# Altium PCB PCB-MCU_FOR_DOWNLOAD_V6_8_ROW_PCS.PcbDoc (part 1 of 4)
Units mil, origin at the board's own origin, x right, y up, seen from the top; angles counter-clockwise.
Board outline not stored, 4 copper layers (Top, GND1, GND2, Bottom), stack 35.4 mil thick; 280 components, 38 nets, 1144 pads, 944 vias.
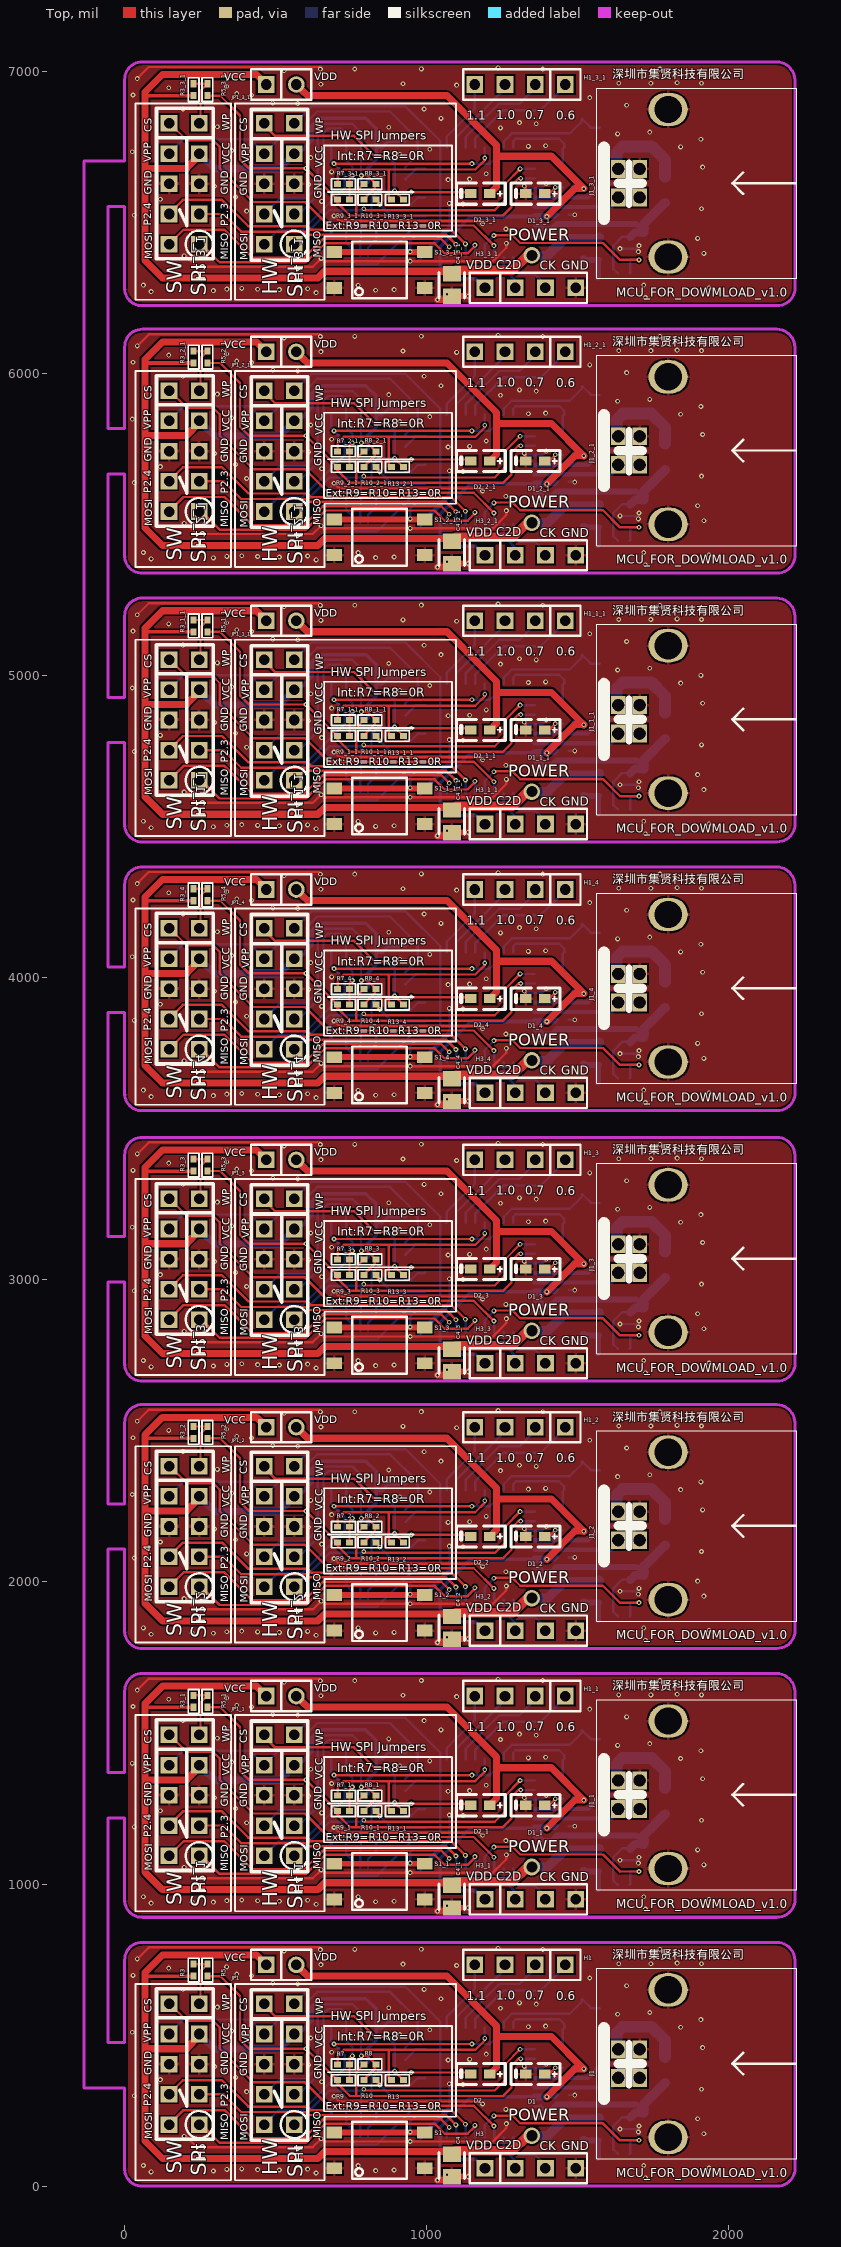
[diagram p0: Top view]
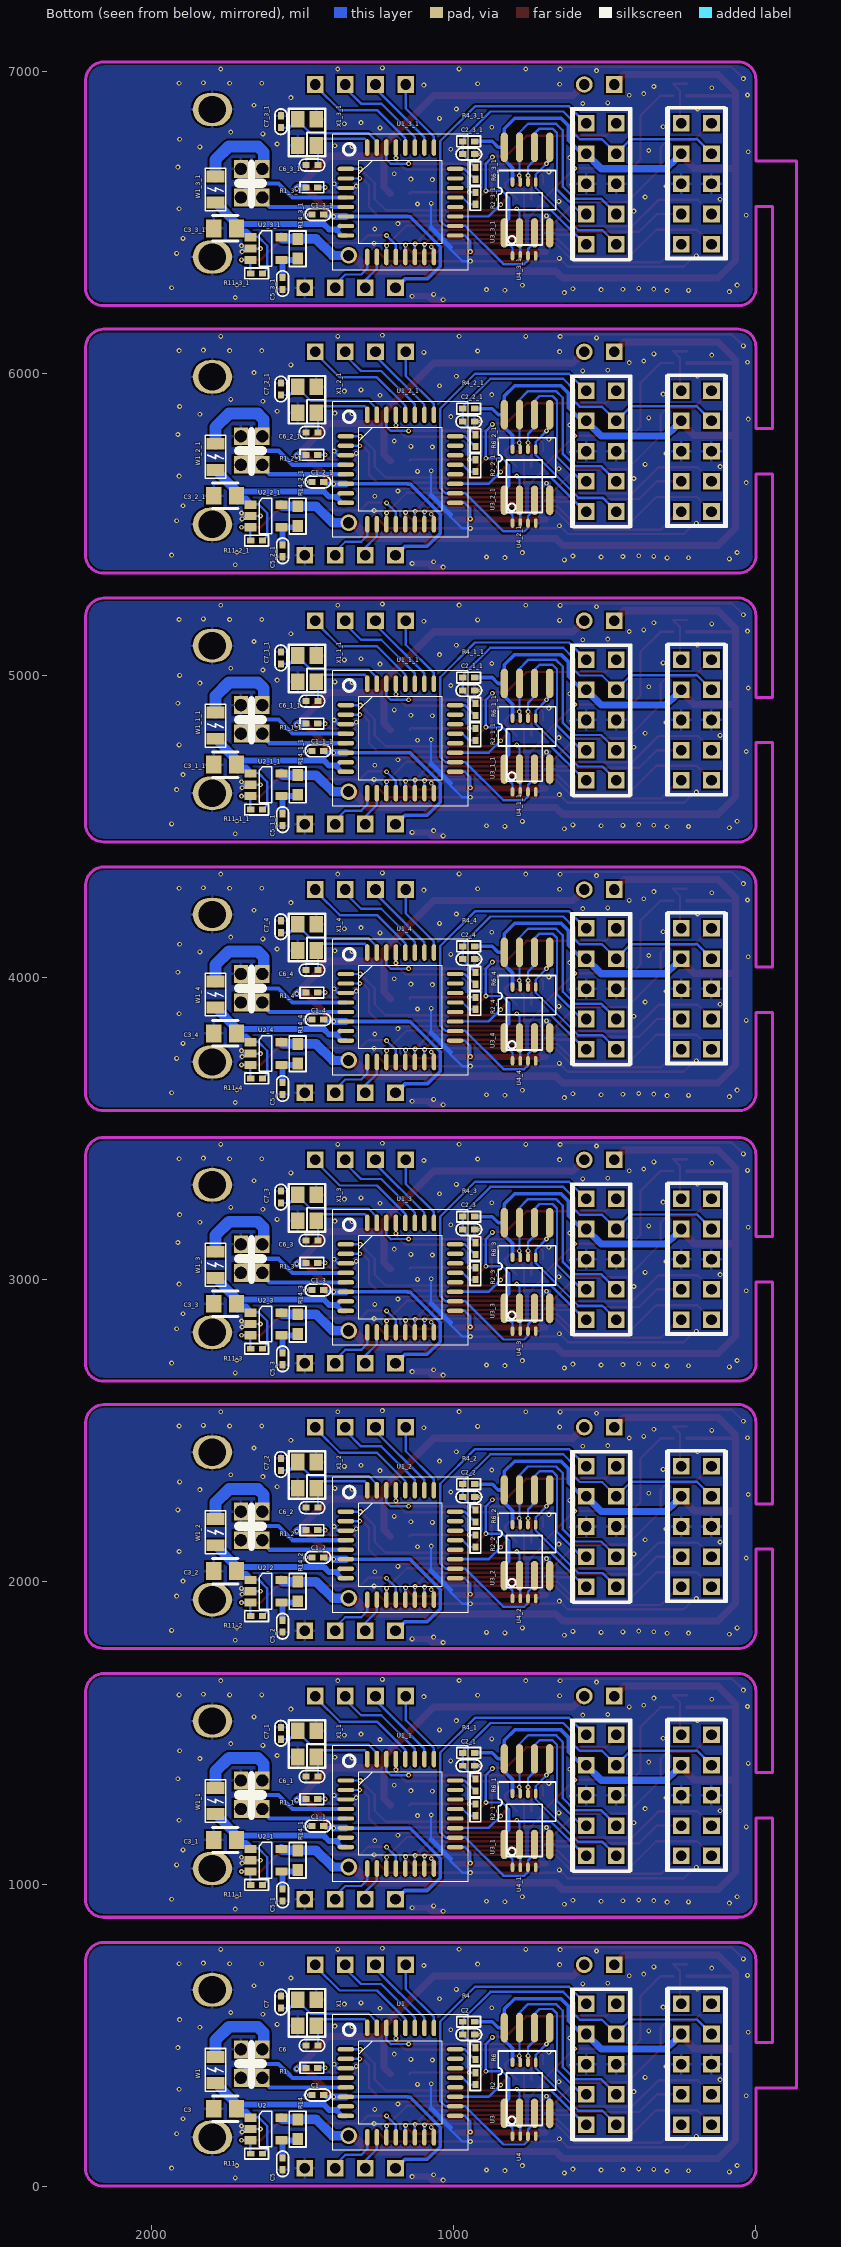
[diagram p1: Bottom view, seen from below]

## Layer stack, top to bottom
Top: signal copper 1.35
Dielectric: dielectric 10, FR-4, Dk 4.3
GND1: signal copper 1.35
Dielectric: dielectric 10, FR-4, Dk 4.3
GND2: signal copper 1.35
Dielectric: dielectric 10, FR-4, Dk 4.3
Bottom: signal copper 1.35

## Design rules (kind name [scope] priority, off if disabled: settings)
Clearance "'Default' PADS rule_18" [All] p1: gap=5.91
Clearance "'Default' PADS rule_15" [IsVia vs IsVia] p2: gap=5.91
ComponentClearance "'Default' PADS rule_12" [All] p1: gap=5.91 collisioncheckmode=3 verticalgap=10 showdistances=FALSE
FlightTimeFalling "'Default' PADS rule_10" [All] p1: maximum=10.00
FlightTimeRising "'Default' PADS rule_9" [All] p1: maximum=10.00
Length "'Default' PADS rule_5" [All] p1: maxlimit=50000 minlimit=0
MatchedLengths "'Default' PADS rule_11" [InNetClass('All Nets')] p1: tolerance=200 checknetsindiffpair=TRUE checkdiffpairvsdiffpair=TRUE checkothers=TRUE
MaxMinImpedance "'Default' PADS rule_8" [All] p1: minimum=50.00 maximum=150.0
ParallelSegment "'Default' PADS rule_7" [All] p1: limit=1000 gap=200
ParallelSegment "'Default' PADS rule_6" [All] p2: limit=1000 gap=200
PlaneClearance "'Default' PADS rule_14" [All] p1: clearance=15
PlaneConnect "Power Plane Connect Style - from global settings" [All] p1: planeconnectstyle=Relief reliefexpansion=20 reliefentries=2 reliefconductorwidth=15 reliefairgap=10
PolygonConnect PolygonConnect_via [IsVia] p1: connectstyle=Direct reliefconductorwidth=10 reliefentries=2 polygonreliefangle="90 Angle"
PolygonConnect PolygonConnect_Pad [All] p2: connectstyle=Relief reliefconductorwidth=10 reliefentries=4 polygonreliefangle="90 Angle"
RoutingLayers "'Default' PADS rule_3" [All] p1: top layer_v5=TRUE mid layer 1_v5=TRUE mid layer 2_v5=TRUE bottom layer_v5=TRUE
RoutingPriority "'Default' PADS rule_2" [All] p1: routingpriority=3
RoutingTopology "'Default' PADS rule" [All] p1: topology=Shortest
RoutingVias "'Default' PADS rule_4" [All] p1: holewidth=37 width=55 viastyle="Through Hole" minholewidth=37 minwidth=55 maxholewidth=37 maxwidth=55
SMDToCorner "'Default' PADS rule_16" [All] p1: distance=59055
SMDToPlane "'Default' PADS rule_17" [All] p1: distance=59055
SilkscreenOverComponentPads [All] p1: minsilkscreentomaskgap=10
SolderMaskExpansion "Solder Mask Expansion from CAM settings" [All] p1: expansion=5
Width "'Default' PADS rule_13" [All] p1: maxlimit=118.11 minlimit=5.91 preferedwidth=7.87
21 further rules are at their usual default settings.

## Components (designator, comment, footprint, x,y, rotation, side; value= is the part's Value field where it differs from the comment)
C1 "C0402" C0402 1450,301.57 r180 bottom
C1_1 "C0402" C0402 1450,1191.57 r180 bottom
C1_1_1 "C0402" C0402 1450,4751.57 r180 bottom
C1_2 "C0402" C0402 1450,2081.57 r180 bottom
C1_2_1 "C0402" C0402 1450,5641.57 r180 bottom
C1_3 "C0402" C0402 1450,2966.57 r180 bottom
C1_3_1 "C0402" C0402 1450,6526.57 r180 bottom
C1_4 "C0402" C0402 1450,3861.57 r180 bottom
C2 "C0402" C0402 950.39,501.57 r0 bottom
C2_1 "C0402" C0402 950.39,1391.57 r0 bottom
C2_1_1 "C0402" C0402 950.39,4951.57 r0 bottom
C2_2 "C0402" C0402 950.39,2281.57 r0 bottom
C2_2_1 "C0402" C0402 950.39,5841.57 r0 bottom
C2_3 "C0402" C0402 950.39,3166.57 r0 bottom
C2_3_1 "C0402" C0402 950.39,6726.57 r0 bottom
C2_4 "C0402" C0402 950.39,4061.57 r0 bottom
C3 "C0805" C0805 1756.69,255.91 r0 bottom
C3_1 "C0805" C0805 1756.69,1145.91 r0 bottom
C3_1_1 "C0805" C0805 1756.69,4705.91 r0 bottom
C3_2 "C0805" C0805 1756.69,2035.91 r0 bottom
C3_2_1 "C0805" C0805 1756.69,5595.91 r0 bottom
C3_3 "C0805" C0805 1756.69,2920.91 r0 bottom
C3_3_1 "C0805" C0805 1756.69,6480.91 r0 bottom
C3_4 "C0805" C0805 1756.69,3815.91 r0 bottom
C4 "C0805" C0805 1083.07,68.11 r270 top
C4_1 "C0805" C0805 1083.07,958.11 r270 top
C4_1_1 "C0805" C0805 1083.07,4518.11 r270 top
C4_2 "C0805" C0805 1083.07,1848.11 r270 top
C4_2_1 "C0805" C0805 1083.07,5408.11 r270 top
C4_3 "C0805" C0805 1083.07,2733.11 r270 top
C4_3_1 "C0805" C0805 1083.07,6293.11 r270 top
C4_4 "C0805" C0805 1083.07,3628.11 r270 top
C5 "C0402" C0402 1566.54,73.62 r90 bottom
C5_1 "C0402" C0402 1566.54,963.62 r90 bottom
C5_1_1 "C0402" C0402 1566.54,4523.62 r90 bottom
C5_2 "C0402" C0402 1566.54,1853.62 r90 bottom
C5_2_1 "C0402" C0402 1566.54,5413.62 r90 bottom
C5_3 "C0402" C0402 1566.54,2738.62 r90 bottom
C5_3_1 "C0402" C0402 1566.54,6298.62 r90 bottom
C5_4 "C0402" C0402 1566.54,3633.62 r90 bottom
C6 "C0402" C0402 1469.29,465.75 r0 bottom
C6_1 "C0402" C0402 1469.29,1355.75 r0 bottom
C6_1_1 "C0402" C0402 1469.29,4915.75 r0 bottom
C6_2 "C0402" C0402 1469.29,2245.75 r0 bottom
C6_2_1 "C0402" C0402 1469.29,5805.75 r0 bottom
C6_3 "C0402" C0402 1469.29,3130.75 r0 bottom
C6_3_1 "C0402" C0402 1469.29,6690.75 r0 bottom
C6_4 "C0402" C0402 1469.29,4025.75 r0 bottom
C7 "C0402" C0402 1572.44,609.06 r90 bottom
C7_1 "C0402" C0402 1572.44,1499.06 r90 bottom
C7_1_1 "C0402" C0402 1572.44,5059.06 r90 bottom
C7_2 "C0402" C0402 1572.44,2389.06 r90 bottom
C7_2_1 "C0402" C0402 1572.44,5949.06 r90 bottom
C7_3 "C0402" C0402 1572.44,3274.06 r90 bottom
C7_3_1 "C0402" C0402 1572.44,6834.06 r90 bottom
C7_4 "C0402" C0402 1572.44,4169.06 r90 bottom
D1 "LED0603" LED0603 1358.27,370.87 r0 top
D1_1 "LED0603" LED0603 1358.27,1260.87 r0 top
D1_1_1 "LED0603" LED0603 1358.27,4820.87 r0 top
D1_2 "LED0603" LED0603 1358.27,2150.87 r0 top
D1_2_1 "LED0603" LED0603 1358.27,5710.87 r0 top
D1_3 "LED0603" LED0603 1358.27,3035.87 r0 top
D1_3_1 "LED0603" LED0603 1358.27,6595.87 r0 top
D1_4 "LED0603" LED0603 1358.27,3930.87 r0 top
D2 "LED0603" LED0603 1177.17,370.87 r0 top
D2_1 "LED0603" LED0603 1177.17,1260.87 r0 top
D2_1_1 "LED0603" LED0603 1177.17,4820.87 r0 top
D2_2 "LED0603" LED0603 1177.17,2150.87 r0 top
D2_2_1 "LED0603" LED0603 1177.17,5710.87 r0 top
D2_3 "LED0603" LED0603 1177.17,3035.87 r0 top
D2_3_1 "LED0603" LED0603 1177.17,6595.87 r0 top
D2_4 "LED0603" LED0603 1177.17,3930.87 r0 top
H1 "H04X1_SQUARE" H04X1_SQUARE 1459.06,732.28 r180 top
H1_1 "H04X1_SQUARE" H04X1_SQUARE 1459.06,1622.28 r180 top
H1_1_1 "H04X1_SQUARE" H04X1_SQUARE 1459.06,5182.28 r180 top
H1_2 "H04X1_SQUARE" H04X1_SQUARE 1459.06,2512.28 r180 top
H1_2_1 "H04X1_SQUARE" H04X1_SQUARE 1459.06,6072.28 r180 top
H1_3 "H04X1_SQUARE" H04X1_SQUARE 1459.06,3397.28 r180 top
H1_3_1 "H04X1_SQUARE" H04X1_SQUARE 1459.06,6957.28 r180 top
H1_4 "H04X1_SQUARE" H04X1_SQUARE 1459.06,4292.28 r180 top
H2 "JH2X5" JH2X5 196.85,403.54 r90 top
H2_1 "JH2X5" JH2X5 196.85,1293.54 r90 top
H2_1_1 "JH2X5" JH2X5 196.85,4853.54 r90 top
H2_2 "JH2X5" JH2X5 196.85,2183.54 r90 top
H2_2_1 "JH2X5" JH2X5 196.85,5743.54 r90 top
H2_3 "JH2X5" JH2X5 196.85,3068.54 r90 top
H2_3_1 "JH2X5" JH2X5 196.85,6628.54 r90 top
H2_4 "JH2X5" JH2X5 196.85,3963.54 r90 top
H3 "H04X1_SQUARE" H04X1_SQUARE 1192.91,59.06 r0 top
H3_1 "H04X1_SQUARE" H04X1_SQUARE 1192.91,949.06 r0 top
H3_1_1 "H04X1_SQUARE" H04X1_SQUARE 1192.91,4509.06 r0 top
H3_2 "H04X1_SQUARE" H04X1_SQUARE 1192.91,1839.06 r0 top
H3_2_1 "H04X1_SQUARE" H04X1_SQUARE 1192.91,5399.06 r0 top
H3_3 "H04X1_SQUARE" H04X1_SQUARE 1192.91,2724.06 r0 top
H3_3_1 "H04X1_SQUARE" H04X1_SQUARE 1192.91,6284.06 r0 top
H3_4 "H04X1_SQUARE" H04X1_SQUARE 1192.91,3619.06 r0 top
H4 "JH2X5" JH2X5 511.81,403.54 r90 top
H4_1 "JH2X5" JH2X5 511.81,1293.54 r90 top
H4_1_1 "JH2X5" JH2X5 511.81,4853.54 r90 top
H4_2 "JH2X5" JH2X5 511.81,2183.54 r90 top
H4_2_1 "JH2X5" JH2X5 511.81,5743.54 r90 top
H4_3 "JH2X5" JH2X5 511.81,3068.54 r90 top
H4_3_1 "JH2X5" JH2X5 511.81,6628.54 r90 top
H4_4 "JH2X5" JH2X5 511.81,3963.54 r90 top
J1 "USB-6" USB-6 1633.86,405.51 r90 top
J1_1 "USB-6" USB-6 1633.86,1295.51 r90 top
J1_1_1 "USB-6" USB-6 1633.86,4855.51 r90 top
J1_2 "USB-6" USB-6 1633.86,2185.51 r90 top
J1_2_1 "USB-6" USB-6 1633.86,5745.51 r90 top
J1_3 "USB-6" USB-6 1633.86,3070.51 r90 top
J1_3_1 "USB-6" USB-6 1633.86,6630.51 r90 top
J1_4 "USB-6" USB-6 1633.86,3965.51 r90 top
JP1 "H02X1" H02X1 468.11,732.28 r0 top
JP1_1 "H02X1" H02X1 468.11,1622.28 r0 top
JP1_1_1 "H02X1" H02X1 468.11,5182.28 r0 top
JP1_2 "H02X1" H02X1 468.11,2512.28 r0 top
JP1_2_1 "H02X1" H02X1 468.11,6072.28 r0 top
JP1_3 "H02X1" H02X1 468.11,3397.28 r0 top
JP1_3_1 "H02X1" H02X1 468.11,6957.28 r0 top
JP1_4 "H02X1" H02X1 468.11,4292.28 r0 top
R1 "R0402" R0402 1470.08,391.34 r0 bottom
R1_1 "R0402" R0402 1470.08,1281.34 r0 bottom
R1_1_1 "R0402" R0402 1470.08,4841.34 r0 bottom
R1_2 "R0402" R0402 1470.08,2171.34 r0 bottom
R1_2_1 "R0402" R0402 1470.08,5731.34 r0 bottom
R1_3 "R0402" R0402 1470.08,3056.34 r0 bottom
R1_3_1 "R0402" R0402 1470.08,6616.34 r0 bottom
R1_4 "R0402" R0402 1470.08,3951.34 r0 bottom
R2 "R0402" R0402 928.35,355.51 r270 bottom
R2_1 "R0402" R0402 928.35,1245.51 r270 bottom
R2_1_1 "R0402" R0402 928.35,4805.51 r270 bottom
R2_2 "R0402" R0402 928.35,2135.51 r270 bottom
R2_2_1 "R0402" R0402 928.35,5695.51 r270 bottom
R2_3 "R0402" R0402 928.35,3020.51 r270 bottom
R2_3_1 "R0402" R0402 928.35,6580.51 r270 bottom
R2_4 "R0402" R0402 928.35,3915.51 r270 bottom
R3 "R0402" R0402 227.95,714.96 r270 top
R3_1 "R0402" R0402 227.95,1604.96 r270 top
R3_1_1 "R0402" R0402 227.95,5164.96 r270 top
R3_2 "R0402" R0402 227.95,2494.96 r270 top
R3_2_1 "R0402" R0402 227.95,6054.96 r270 top
R3_3 "R0402" R0402 227.95,3379.96 r270 top
R3_3_1 "R0402" R0402 227.95,6939.96 r270 top
R3_4 "R0402" R0402 227.95,4274.96 r270 top
R4 "R0402" R0402 950.39,544.09 r180 bottom
R4_1 "R0402" R0402 950.39,1434.09 r180 bottom
R4_1_1 "R0402" R0402 950.39,4994.09 r180 bottom
R4_2 "R0402" R0402 950.39,2324.09 r180 bottom
R4_2_1 "R0402" R0402 950.39,5884.09 r180 bottom
R4_3 "R0402" R0402 950.39,3209.09 r180 bottom
R4_3_1 "R0402" R0402 950.39,6769.09 r180 bottom
R4_4 "R0402" R0402 950.39,4104.09 r180 bottom
R5 "R0402" R0402 274.02,714.96 r270 top
R5_1 "R0402" R0402 274.02,1604.96 r270 top
R5_1_1 "R0402" R0402 274.02,5164.96 r270 top
R5_2 "R0402" R0402 274.02,2494.96 r270 top
R5_2_1 "R0402" R0402 274.02,6054.96 r270 top
R5_3 "R0402" R0402 274.02,3379.96 r270 top
R5_3_1 "R0402" R0402 274.02,6939.96 r270 top
R5_4 "R0402" R0402 274.02,4274.96 r270 top
R6 "R0402" R0402 928.35,438.19 r90 bottom
R6_1 "R0402" R0402 928.35,1328.19 r90 bottom
R6_1_1 "R0402" R0402 928.35,4888.19 r90 bottom
R6_2 "R0402" R0402 928.35,2218.19 r90 bottom
R6_2_1 "R0402" R0402 928.35,5778.19 r90 bottom
R6_3 "R0402" R0402 928.35,3103.19 r90 bottom
R6_3_1 "R0402" R0402 928.35,6663.19 r90 bottom
R6_4 "R0402" R0402 928.35,3998.19 r90 bottom
R7 "R0402" R0402 724.41,402.76 r180 top
R7_1 "R0402" R0402 724.41,1292.76 r180 top
R7_1_1 "R0402" R0402 724.41,4852.76 r180 top
R7_2 "R0402" R0402 724.41,2182.76 r180 top
R7_2_1 "R0402" R0402 724.41,5742.76 r180 top
R7_3 "R0402" R0402 724.41,3067.76 r180 top
R7_3_1 "R0402" R0402 724.41,6627.76 r180 top
R7_4 "R0402" R0402 724.41,3962.76 r180 top
R8 "R0402" R0402 811.81,402.76 r0 top
R8_1 "R0402" R0402 811.81,1292.76 r0 top
R8_1_1 "R0402" R0402 811.81,4852.76 r0 top
R8_2 "R0402" R0402 811.81,2182.76 r0 top
R8_2_1 "R0402" R0402 811.81,5742.76 r0 top
R8_3 "R0402" R0402 811.81,3067.76 r0 top
R8_3_1 "R0402" R0402 811.81,6627.76 r0 top
R8_4 "R0402" R0402 811.81,3962.76 r0 top
R9 "R0402" R0402 724.41,351.18 r180 top
R9_1 "R0402" R0402 724.41,1241.18 r180 top
R9_1_1 "R0402" R0402 724.41,4801.18 r180 top
R9_2 "R0402" R0402 724.41,2131.18 r180 top
R9_2_1 "R0402" R0402 724.41,5691.18 r180 top
R9_3 "R0402" R0402 724.41,3016.18 r180 top
R9_3_1 "R0402" R0402 724.41,6576.18 r180 top
R9_4 "R0402" R0402 724.41,3911.18 r180 top
R10 "R0402" R0402 811.81,351.18 r180 top
R10_1 "R0402" R0402 811.81,1241.18 r180 top
R10_1_1 "R0402" R0402 811.81,4801.18 r180 top
R10_2 "R0402" R0402 811.81,2131.18 r180 top
R10_2_1 "R0402" R0402 811.81,5691.18 r180 top
R10_3 "R0402" R0402 811.81,3016.18 r180 top
R10_3_1 "R0402" R0402 811.81,6576.18 r180 top
R10_4 "R0402" R0402 811.81,3911.18 r180 top
R11 "R0402" R0402 1652.36,107.09 r0 bottom
R11_1 "R0402" R0402 1652.36,997.09 r0 bottom
R11_1_1 "R0402" R0402 1652.36,4557.09 r0 bottom
R11_2 "R0402" R0402 1652.36,1887.09 r0 bottom
R11_2_1 "R0402" R0402 1652.36,5447.09 r0 bottom
R11_3 "R0402" R0402 1652.36,2772.09 r0 bottom
R11_3_1 "R0402" R0402 1652.36,6332.09 r0 bottom
R11_4 "R0402" R0402 1652.36,3667.09 r0 bottom
R13 "R0402" R0402 902.76,351.18 r0 top
R13_1 "R0402" R0402 902.76,1241.18 r0 top
R13_1_1 "R0402" R0402 902.76,4801.18 r0 top
R13_2 "R0402" R0402 902.76,2131.18 r0 top
R13_2_1 "R0402" R0402 902.76,5691.18 r0 top
R13_3 "R0402" R0402 902.76,3016.18 r0 top
R13_3_1 "R0402" R0402 902.76,6576.18 r0 top
R13_4 "R0402" R0402 902.76,3911.18 r0 top
R14 "R0603" R0603 1516.93,188.58 r270 bottom
R14_1 "R0603" R0603 1516.93,1078.58 r270 bottom
R14_1_1 "R0603" R0603 1516.93,4638.58 r270 bottom
R14_2 "R0603" R0603 1516.93,1968.58 r270 bottom
R14_2_1 "R0603" R0603 1516.93,5528.58 r270 bottom
R14_3 "R0603" R0603 1516.93,2853.58 r270 bottom
R14_3_1 "R0603" R0603 1516.93,6413.58 r270 bottom
R14_4 "R0603" R0603 1516.93,3748.58 r270 bottom
S1 "4PIN_SWITCH_SMD_4.5MM" 4PIN_SWITCH_SMD_4.5MM 843.7,118.11 r90 top
S1_1 "4PIN_SWITCH_SMD_4.5MM" 4PIN_SWITCH_SMD_4.5MM 843.7,1008.11 r90 top
S1_1_1 "4PIN_SWITCH_SMD_4.5MM" 4PIN_SWITCH_SMD_4.5MM 843.7,4568.11 r90 top
S1_2 "4PIN_SWITCH_SMD_4.5MM" 4PIN_SWITCH_SMD_4.5MM 843.7,1898.11 r90 top
S1_2_1 "4PIN_SWITCH_SMD_4.5MM" 4PIN_SWITCH_SMD_4.5MM 843.7,5458.11 r90 top
S1_3 "4PIN_SWITCH_SMD_4.5MM" 4PIN_SWITCH_SMD_4.5MM 843.7,2783.11 r90 top
S1_3_1 "4PIN_SWITCH_SMD_4.5MM" 4PIN_SWITCH_SMD_4.5MM 843.7,6343.11 r90 top
S1_4 "4PIN_SWITCH_SMD_4.5MM" 4PIN_SWITCH_SMD_4.5MM 843.7,3678.11 r90 top
U1 "LQFP-32" LQFP-32 1357.09,452.76 r180 bottom
U1_1 "LQFP-32" LQFP-32 1357.09,1342.76 r180 bottom
U1_1_1 "LQFP-32" LQFP-32 1357.09,4902.76 r180 bottom
U1_2 "LQFP-32" LQFP-32 1357.09,2232.76 r180 bottom
U1_2_1 "LQFP-32" LQFP-32 1357.09,5792.76 r180 bottom
U1_3 "LQFP-32" LQFP-32 1357.09,3117.76 r180 bottom
U1_3_1 "LQFP-32" LQFP-32 1357.09,6677.76 r180 bottom
U1_4 "LQFP-32" LQFP-32 1357.09,4012.76 r180 bottom
U2 "SOT23-5_SGM2019" SOT23-5_SGM2019 1673.23,188.98 r180 bottom
U2_1 "SOT23-5_SGM2019" SOT23-5_SGM2019 1673.23,1078.98 r180 bottom
U2_1_1 "SOT23-5_SGM2019" SOT23-5_SGM2019 1673.23,4638.98 r180 bottom
U2_2 "SOT23-5_SGM2019" SOT23-5_SGM2019 1673.23,1968.98 r180 bottom
U2_2_1 "SOT23-5_SGM2019" SOT23-5_SGM2019 1673.23,5528.98 r180 bottom
U2_3 "SOT23-5_SGM2019" SOT23-5_SGM2019 1673.23,2853.98 r180 bottom
U2_3_1 "SOT23-5_SGM2019" SOT23-5_SGM2019 1673.23,6413.98 r180 bottom
U2_4 "SOT23-5_SGM2019" SOT23-5_SGM2019 1673.23,3748.98 r180 bottom
U3 "SO8W" SO8W 757.48,382.68 r180 bottom
U3_1 "SO8W" SO8W 757.48,1272.68 r180 bottom
U3_1_1 "SO8W" SO8W 757.48,4832.68 r180 bottom
U3_2 "SO8W" SO8W 757.48,2162.68 r180 bottom
U3_2_1 "SO8W" SO8W 757.48,5722.68 r180 bottom
U3_3 "SO8W" SO8W 757.48,3047.68 r180 bottom
U3_3_1 "SO8W" SO8W 757.48,6607.68 r180 bottom
U3_4 "SO8W" SO8W 757.48,3942.68 r180 bottom
U4 "SO8-TSS" SO8-TSS 805.51,165.35 r90 bottom
U4_1 "SO8-TSS" SO8-TSS 805.51,1055.35 r90 bottom
U4_1_1 "SO8-TSS" SO8-TSS 805.51,4615.35 r90 bottom
U4_2 "SO8-TSS" SO8-TSS 805.51,1945.35 r90 bottom
U4_2_1 "SO8-TSS" SO8-TSS 805.51,5505.35 r90 bottom
U4_3 "SO8-TSS" SO8-TSS 805.51,2830.35 r90 bottom
U4_3_1 "SO8-TSS" SO8-TSS 805.51,6390.35 r90 bottom
U4_4 "SO8-TSS" SO8-TSS 805.51,3725.35 r90 bottom
W1 "SMD0805" SMD0805 1788.98,384.65 r90 bottom
W1_1 "SMD0805" SMD0805 1788.98,1274.65 r90 bottom
W1_1_1 "SMD0805" SMD0805 1788.98,4834.65 r90 bottom
W1_2 "SMD0805" SMD0805 1788.98,2164.65 r90 bottom
W1_2_1 "SMD0805" SMD0805 1788.98,5724.65 r90 bottom
W1_3 "SMD0805" SMD0805 1788.98,3049.65 r90 bottom
W1_3_1 "SMD0805" SMD0805 1788.98,6609.65 r90 bottom
W1_4 "SMD0805" SMD0805 1788.98,3944.65 r90 bottom
X1 "3225_4" 3225_4 1485.83,573.62 r90 bottom
X1_1 "3225_4" 3225_4 1485.83,1463.62 r90 bottom
X1_1_1 "3225_4" 3225_4 1485.83,5023.62 r90 bottom
X1_2 "3225_4" 3225_4 1485.83,2353.62 r90 bottom
X1_2_1 "3225_4" 3225_4 1485.83,5913.62 r90 bottom
X1_3 "3225_4" 3225_4 1485.83,3238.62 r90 bottom
X1_3_1 "3225_4" 3225_4 1485.83,6798.62 r90 bottom
X1_4 "3225_4" 3225_4 1485.83,4133.62 r90 bottom

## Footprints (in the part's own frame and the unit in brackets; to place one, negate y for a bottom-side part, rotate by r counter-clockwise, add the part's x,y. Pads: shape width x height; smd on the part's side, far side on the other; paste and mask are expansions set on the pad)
4PIN_SWITCH_SMD_4.5MM [mm]
  rect 1x1.3 smd: 1(-1.5,3.8) 2(1.5,3.8) 3(-1.5,-3.8) 4(1.5,-3.8)
  silkscreen extent -2.37,-2.3 2.4,2.3
3225_4 [mm]
  rect 1.4x1.15 smd: 1(-1.1,-0.782) 2(1.1,-0.782) 3(1.1,0.782) 4(-1.1,0.782)
  silkscreen extent -2,-1.52 2,1.52
C0402 [mm]
  rect 0.6x0.5 smd: 1(-0.5,0) 2(0.5,0)
  silkscreen extent -1.07,-0.5 1.07,0.5
C0805 [mil]
  rect 50.98x59.02 smd: 1(-37.48,0) 2(37.48,0)
  silkscreen extent -43,-42 43,42
H02X1 [mil]
  rect 55x55 / inner round 55 / far side rect 55x55 hole 35: 1(0,0)
  round 55 hole 35: 2(100,0)
  silkscreen extent -50,-50 150,50
H04X1_SQUARE [mil]
  rect 55x55 hole 35: 1(0,0) 2(100,0) 3(200,0) 4(300,0)
  silkscreen extent -50,-50 338,50
JH2X5 [mil]
  rect 55x55 hole 35: 1(-200,-50) 2(-200,50) 3(-100,-50) 4(-100,50) 5(0,-50) 6(0,50) 7(100,-50) 8(100,50) 9(200,-50) 10(200,50)
  silkscreen extent -245,-95 -155,-5
LED0603 [mil]
  rect 38x30 smd paste+1.18 mask+1.18: 1(-31,0) 2(31.99,0)
  silkscreen extent -79,-35 83,35
LQFP-32 [mm]
  oval 1.4x0.37 smd: 1(0,0) 2(0,-0.8) 3(0,-1.6) 4(0,-2.4) 5(0,-3.2) 6(0,-4) 7(0,-4.8) 8(0,-5.6) 17(9.2,-5.6) 18(9.2,-4.8) 19(9.2,-4) 20(9.2,-3.2) 21(9.2,-2.4) 22(9.2,-1.6) 23(9.2,-0.8) 24(9.2,0)
  oval 0.37x1.4 smd: 9(1.8,-7.4) 10(2.6,-7.4) 11(3.4,-7.4) 12(4.2,-7.4) 13(5,-7.4) 14(5.8,-7.4) 15(6.6,-7.4) 16(7.4,-7.4) 25(7.4,1.8) 26(6.6,1.8) 27(5.8,1.8) 28(5,1.8) 29(4.2,1.8) 30(3.4,1.8) 31(2.6,1.8) 32(1.8,1.8)
  silkscreen extent -1.1,-8.5 10.3,2.9
R0402 [mm]
  rect 0.6x0.5 smd: 1(-0.5,0) 2(0.5,0)
  silkscreen extent -1,-0.45 1,0.45
R0603 [mm]
  rect 1x0.9 smd: 1(-0.826,0) 2(0.826,0)
  silkscreen extent -1.5,-0.7 1.5,0.7
SMD0805 [mm]
  rect 1x1.5 smd paste-0.1 mask-0.1: 1(-1.1,0) 2(1.1,0)
  silkscreen extent -1.8,-0.85 1.8,0.85
SO8-TSS [mm]
  oval 0.8x0.3 smd: 1(0,0) 2(0,-0.65) 3(0,-1.3) 4(0,-1.95) 5(6.2,-1.95) 6(6.2,-1.3) 7(6.2,-0.65) 8(6.2,0)
  silkscreen extent 0.9,-2.5 5.3,0.5
SO8W [mil]
  oval 24x97.62 smd paste-11.81 mask-11.81: 1(-75,-141.73) 2(-25,-141.73) 3(25,-141.73) 4(75,-141.73) 5(75,141.73) 6(25,141.73) 7(-25,141.73) 8(-75,141.73)
  silkscreen extent -95,-65 95,65
SOT23-5_SGM2019 [mm]
  rect 1x0.69 smd: 1(0,0.95) 2(0,0) 3(0,-0.95) 4(2.6,-0.95) 5(2.6,0.95)
  silkscreen extent 0.76,-1.5 1.8,1.5
USB-6 [mm]
  rect 1.5x1.2 / inner rect 0x0 / far side rect 1.5x1.2 hole 1: 1(1.2,0) 2(-1.2,0) 3(-1.2,-1.8) 4(1.2,-1.8)
  oval 2.8x3.3 / inner round 0 / far side oval 2.8x3.3 hole 2.3: 5(6.2,-4.2) 6(-6.2,-4.2)
  silkscreen extent -8,-15 8,1.8

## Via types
v1: diameter 16/16/16/16 (per signal layer), hole 8, Top to Bottom, 936 vias
v2: diameter 55/55/55/55 (per signal layer), hole 37, Top to Bottom, 8 vias

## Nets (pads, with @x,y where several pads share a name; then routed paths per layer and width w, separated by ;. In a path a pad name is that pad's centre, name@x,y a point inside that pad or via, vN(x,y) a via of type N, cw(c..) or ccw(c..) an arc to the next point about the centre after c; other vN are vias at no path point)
+5V: C3.1 R11.1 U1.7 U1.8 U2.1 W1.1 | length 791.9
  Bottom w7.87: R11.1@1632.68,107.09 1619.29,120.47 1617.72,120.47 1617.72,198.57 1646.88,227.73 1647.02,227.73 1647.24,227.95 1673.23,227.95 1674.02,227.18 U2.1@1673.23,226.38
  Bottom w9.84: U1.7@1357.09,263.78 U1.7@1376.38,263.78
  Bottom w15.75: U1.8@1357.09,232.28 1370.87,232.28 1389.37,250.79 U1.7@1376.38,263.78
  Bottom w19.68: 1389.37,250.79 1391.14,252.56 1412.8,252.56 1430.31,270.08 1692.05,270.08 1718.9,256.07 C3.1@1719.21,255.91
  Bottom w27.56: U2.1@1674.02,227.18 1688.98,242.52 C3.1@1712.99,242.52
  Bottom w31.5: C3.1@1712.99,242.52 1718.82,242.52 C3.1@1718.9,245.19 ; W1.1@1788.98,341.34 1718.9,271.26 1718.9,256.07 1718.9,255.91 C3.1@1718.9,245.19 ; C3.1@1718.9,245.19 1718.9,243.23 C3.1@1719.21,255.91 C3.1@1718.9,245.19
C2CK: H3.3 U1.9 | length 186.3
  Bottom w7.87: U1.9@1286.22,161.42 1286.22,123.62 1306.5,103.35 1359.06,103.35 1398.13,64.27 1400.79,61.61 H3.3@1392.91,59.06
C2D: H3.2 U1.10 | length 130.9
  Bottom w7.87: U1.10@1254.72,161.42 1254.72,122.05 1297.01,79.76 1297.01,59.26 1300.59,59.26 H3.2@1292.91,59.06
GGND: C1.1 C2.1 C3.2 C4.2 C5.1 C6.2 C7.2 D1.1 H2.5 H2.6 H3.4 H4.5 H4.6 J1.4 J1.5 J1.6 S1.1 S1.3 U1.3 U2.2 U3.4 U4.4 X1.2 X1.4 | length 2977.8
  Top w7.87: v1(41.34,751.97) 79.53,790.16 644.09,790.16 648.03,786.22 v1(648.03,783.07) ; v1(196.85,164.96) 202.76,164.96 238.58,129.13 622.83,129.13 v1@648.83,155.13 ; v1(692.91,297.24) 693.31,297.24 710.63,279.92 1176.77,279.92 v1(1185.04,271.65) ; v1(1263.78,206.69) 1263.39,192.13 1218.9,147.64 v1(944.88,147.64) 660.24,147.64 649.21,154.89 v1@648.83,155.13 ; v1(1322.83,396.06) 1327.27,391.63 D1.1@1327.27,370.87 ; v1@648.83,155.13 646.46,156.69 v1(650.39,156.69) v1@648.83,155.13
  Top w19.68: C4.2@1083.07,30.63 1083.94,31.5 v1(1137.8,31.5)
  Top w22.05: v1(1035.43,19.69) 1072.13,19.69 1078.39,25.95 C4.2@1083.07,30.63
  Bottom w7.87: v1(692.91,297.24) 692.91,296.65 U3.4@682.48,286.22 ; v1(910.63,501.57) 911.02,501.57 C2.1@930.71,501.57 ; v1(944.88,147.64) 972.05,147.64 1011.02,186.61 1011.02,193.7 ; v1(1074.8,338.58) 1075.2,338.19 1075.2,257.87 ; v1(1322.83,396.06) 1328.6,390.3 1328.6,390.01 1328.85,389.76 U1.3@1357.09,389.76 1381.89,389.76 v1(1395.67,403.54) ; C1.1@1469.68,301.58 1489.76,301.58 v1(1490.16,301.18) ; v1(1639.76,188.98) U2.2@1673.23,188.98 1690.94,188.98 U2.2@1691.73,188.19 ; v1(1700.79,179.13) U2.2@1691.73,188.19 ; v1(1702.76,198.82) 1692.13,188.19 U2.2@1691.73,188.19 ; U3.4@682.48,286.22 U3.4@682.48,240.94 682.48,238 686.32,241.84 U3.4@682.48,286.22
  Bottom w15.75: 1011.02,193.7 1075.2,257.87
  other v1: 1723.62,27.17 1066.93,37.4 633.86,43.31 87.4,46.85 293.7,50 222.83,50.79 830.71,51.18 512.2,53.15 891.73,53.15 338.19,55.12 440.16,54.72 605.51,56.3 387.8,57.09 1934.25,59.45 61.81,68.11 772.83,67.72 1718.5,68.11 1917.32,173.23 1896.46,222.83 1261.81,253.94 31.5,299.21 403.54,312.99 1909.45,320.87 1120.08,336.61 651.97,345.28 118.11,352.36 366.54,359.84 297.24,395.67 608.27,401.18 1070.87,417.32 1141.73,419.29 1196.85,437.01 685.04,442.91 1913.39,458.66 616.14,490.16 25.2,509.45 354.33,513.78 1009.84,517.72 1840.55,525.59 1336.61,527.56 1393.31,529.53 1584.65,535.43 1907.48,551.18 1631.89,568.9 1738.19,574.8 1244.09,588.58 874.02,590.55 307.09,592.52 1362.2,602.36 1307.09,606.3 1047.24,620.08 991.34,651.18 192.91,651.57 1661.42,663.39 572.83,669.29 490.16,671.26 1539.37,688.98 419.29,696.46 27.56,697.64 371.26,701.97 145.67,721.65 337.4,725.59 1098.82,730.31 649.61,733.07 921.26,735.04 1635.83,736.22 1742.13,736.22 1909.45,736.22 1828.74,738.19 527.56,778.35 761.81,783.46 982.28,783.86 1383.86,783.46 1771.65,783.46 1236.22,787.4
HW_HOLD: R10.1 U1.19 | length 188.6
  Top w7.87: R10.1@831.5,351.18 832.28,350.39 832.28,348.03 838.39,341.93 838.39,340.75 v1(844.49,334.65)
  Bottom w7.87: v1(844.49,334.65) 845.28,334.65 884.65,295.28 U1.19@994.88,295.28
HW_HOLD_1: H4.4 R8.2 R10.2 U3.7 U4.7 | length 860.6
  Top w7.87: v1(783.46,431.1) 803.15,431.1 R8.2@831.5,402.76 ; R10.2@792.13,351.18 792.13,352.76 828.74,389.37 828.74,401.22 829.12,401.59 R8.2@829.12,401.95
  Bottom w7.87: H4.4@461.81,303.54 511.42,353.15 511.42,353.94 598.82,353.94 638.58,393.7 638.58,542.91 638.98,543.31 638.98,580.31 661.02,602.36 753.9,602.36 785.12,571.14 785.12,527.05 U3.7@782.48,524.41 782.48,431.1 v1@782.48,430.31 ; U4.7@779.92,409.45 782.48,412.01 v1@782.48,430.31 ; v1(783.46,431.1) 782.68,430.31 v1@782.48,430.31
HW_MISO: H4.1 U1.1 U3.2 U4.2 | length 1088.6
  Top w7.87: v1(791.34,320.87) 795.67,316.54 795.67,316.34 1225.2,316.34 1261.42,352.56 1261.42,405.12 v1(1309.06,452.76)
  Bottom w7.87: H4.1@565.4,210.1 569.82,210.1 570.87,209.06 677.97,316.16 782.48,316.16 782.48,313.78 ; U4.2@779.92,165.35 779.92,219.69 782.48,222.24 U3.2@782.48,240.94 782.48,313.78 ; v1(791.34,320.87) 784.25,313.78 782.48,313.78 ; v1(1309.06,452.76) U1.1@1357.09,452.76
  Bottom w11.81: H4.1@561.81,203.54 565.4,207.13 H4.1@565.4,210.1
HW_MOSI: H4.2 U1.30 U3.5 U4.5 | length 1074.3
  Top w7.87: v1(692.91,470.47) v1(1149.61,470.47)
  Bottom w7.87: H4.2@463.55,206.92 464.09,206.92 465.75,208.58 466.54,208.58 507.56,249.61 587.8,249.61 728.74,390.55 U4.5@728.74,409.45 728.74,433.86 692.52,470.08 v1@692.13,470.47 ; U3.5@682.48,524.41 683.46,523.43 683.46,479.13 v1@692.13,470.47 ; v1(692.91,470.47) v1@692.13,470.47 ; v1(1149.61,470.47) 1208.27,470.47 1208.66,470.08 1223.23,484.65 U1.30@1223.23,523.62
  Bottom w11.81: H4.2@461.81,203.54 H4.2@463.55,206.92
HW_NSS: R7.2 R13.1 U1.29 | length 677.5
  Top w7.87: R7.2@704.72,402.76 704.72,430.31 725.2,450.79 874.8,450.79 ; R13.1@874.8,351.57 874.8,450.79 ; v1(1191.73,488.98) 1192.52,488.19 1192.52,482.68 1160.63,450.79 874.8,450.79
  Bottom w7.87: v1(1191.73,488.98) U1.29@1191.73,523.62
HW_NSS_1: H4.10 R13.2 U3.1 U4.1 | length 921.4
  Top w7.87: H4.10@461.81,603.54 460.63,603.54 458.27,601.18 458.86,600.59 497.24,562.2 759.45,562.2 826.77,494.88 869.29,494.88 v1(872.05,492.13) ; v1(893.7,379.92) R13.2@922.44,351.18
  Bottom w7.87: U4.1@805.51,165.35 805.51,192.13 832.48,219.09 U3.1@832.48,240.94 833.07,241.54 833.07,272.05 816.93,288.19 816.93,357.09 839.76,379.92 v1(893.7,379.92) 893.7,470.47 v1(872.05,492.13)
HW_SCK: R5.2 R8.1 R9.2 U1.2 | length 1562.8
  Top w7.87: R5.2@274.02,695.28 316.14,695.28 381.89,629.53 381.89,484.25 411.42,454.72 v1(600.39,454.72) 701.97,353.15 701.97,351.18 701.97,342.52 706.5,337.99 ; R9.2@704.72,351.18 706.5,349.41 706.5,337.99 ; R8.1@792.13,402.76 790.55,402.76 767.5,379.7 767.5,350.79 767.13,301.57 766.54,298.43 ; v1(1311.02,421.26) 1309.45,422.83 1305.12,422.83 1301.77,419.49 1300.98,419.49 1280.51,399.02 1280.51,326.57 1252.36,298.43 766.54,298.43 ; 706.5,337.99 743.5,300.98 746.06,298.43 766.54,298.43
  Bottom w7.87: v1(1311.02,421.26) U1.2@1357.09,421.26
HW_SCK_1: H4.3 R7.1 R9.1 U3.6 U4.6 | length 659.6
  Top w7.87: R9.1@744.09,351.18 R7.1@744.09,402.76 744.09,423.62 751.18,430.71 753.54,430.71 v1(753.94,431.1)
  Bottom w7.87: H4.3@561.81,303.54 575.2,303.54 575.98,302.76 658.27,385.04 658.27,571.26 673.23,586.22 715.94,586.22 732.48,569.69 U3.6@732.48,524.41 733.86,523.03 733.86,480.71 754.33,460.24 754.33,431.1 v1(753.94,431.1) 754.33,430.71 U4.6@754.33,409.45
HW_WP: H4.9 U1.18 U3.3 U4.3 | length 1272.4
  Bottom w7.87: H4.9@561.81,603.54 618.11,659.84 929.53,659.84 1044.49,544.88 1044.49,281.5 1026.77,263.78 U1.18@994.88,263.78 994.09,264.57 962.6,264.57 835.83,137.8 766.54,137.8 754.33,150 U4.3@754.33,165.35 754.33,187.8 733.07,209.06 733.07,240.35 U3.3@732.48,240.94
LDO_EN: R11.2 U1.12 U2.3 | length 673.1
  Top w7.87: v1(1222.44,232.28) 1223.62,233.46 1283.86,233.46 1309.65,207.68 1583.27,207.68 1639.76,151.18 1640.16,151.57 v1(1702.76,151.57)
  Bottom w7.87: U1.12@1191.73,161.42 1191.73,201.18 1222.44,231.89 v1(1222.44,232.28) ; R11.2@1672.05,107.09 1673.23,108.27 U2.3@1673.23,151.57 v1(1702.76,151.57)
N3634951: J1.3 U1.4 | length 392.4
  Bottom w13.78: U1.4@1357.09,358.27 1534.25,358.27 1551.18,375.2 1580.71,404.72 1668.9,404.72 1704.72,368.9 J1.3@1704.72,358.27
N3635015: J1.2 U1.5 | length 294
  Bottom w13.78: U1.5@1357.09,326.77 1609.45,326.77 1633.46,350.79 1633.86,351.18 J1.2@1633.86,358.27
N3708200: C5.2 R14.2 U2.4 | length 114.1
  Bottom w19.68: R14.2@1516.93,156.08 1522.66,156.08 1527.17,151.57 U2.4@1566.54,151.57 ; C5.2@1566.54,93.31 U2.4@1566.54,151.57 ; U2.4@1570.87,151.57 U2.4@1566.54,151.57
N3716250: J1.1 W1.2 | length 299.9
  Bottom w39.37: J1.1@1633.86,452.76 1629.14,454.78 1628.99,454.93 1628.99,508.12 1648.43,527.56 1744.09,527.56 1788.98,482.68 W1.2@1788.98,427.95
N3755063: D1.2 R1.1 | length 69.9
  Top w7.87: D1.2@1390.26,370.87 1390.26,372.44 1405.91,372.44 v1(1425.2,391.73)
  Bottom w7.87: v1(1425.2,391.73) 1450,391.73 R1.1@1450.39,391.34
N16414028: S1.2 S1.4 U1.17 | length 440.8
  Top w7.87: v1(944.88,179.13) 991.34,179.13 S1.4@993.31,177.17
  Top w19.68: S1.2@694.09,177.17 944.88,177.17 S1.4@993.31,177.17
  Bottom w7.87: v1(944.88,179.13) 945.28,179.53 945.28,214.17 963.39,232.28 U1.17@994.88,232.28
N16416150: H2.9 R3.1 R5.1 | length 188.4
  Top w7.87: R3.1@227.95,734.65 R5.1@274.02,734.65 251.18,711.81 251.18,611.02 246.85,606.69 H2.9@246.85,603.54
N16446401: R6.1 U1.24 | length 80.7
  Bottom w7.87: R6.1@928.35,418.5 929.92,418.5 964.17,452.76 U1.24@994.88,452.76
N16626884: C6.1 U1.32 X1.1 | length 272.5
  Bottom w7.87: U1.32@1286.22,523.62 1286.22,544.09 1294.88,552.76 1438.58,552.76 1455.04,536.3 X1.1@1455.04,530.31 1455.04,524.33 1449.61,518.9 C6.1@1449.61,465.75
N16627190: C7.1 U1.31 X1.3 | length 384.8
  Bottom w7.87: U1.31@1254.72,523.62 1254.72,543.7 1281.5,570.47 1473.62,570.47 1512.99,609.84 1512.99,616.93 1512.99,617.32 1516.22,617.32 X1.3@1516.61,616.93 1543.31,590.24 1543.31,589.37 C7.1@1572.44,589.37
N16638101: H1.1 U1.28 | length 409.9
  Bottom w7.87: U1.28@1160.24,523.62 1160.24,553.54 1254.33,647.64 1377.56,647.64 1450.79,720.87 1459.06,720.87 1459.45,720.87 1459.45,724.02 H1.1@1459.06,732.28
N16638386: H1.2 U1.27 | length 343.3
  Bottom w7.87: U1.27@1128.74,523.62 1128.74,557.48 1240.16,668.9 1307.09,668.9 1359.06,720.87 H1.2@1359.06,732.28
N16638553: H1.3 U1.26 | length 275.7
  Bottom w7.87: U1.26@1097.24,523.62 1097.24,557.09 1259.06,718.9 H1.3@1259.06,732.28
N16638723: H1.4 U1.25 | length 247.3
  Bottom w7.87: U1.25@1065.75,523.62 1065.75,559.45 1159.06,652.76 H1.4@1159.06,732.28
N16668632: R2.2 U1.21 | length 75.8
  Bottom w7.87: R2.2@928.35,335.83 948.82,335.83 970.47,357.48 994.09,357.48 U1.21@994.88,358.27
N16675349: D2.1 R2.1 | length 221.6
  Top w7.87: v1(948.82,375.98) 1143.31,375.98 1146.17,373.13 D2.1@1146.17,370.87
  Bottom w7.87: R2.1@928.35,375.2 948.03,375.2 v1(948.82,375.98)
P2.3: H2.3 U1.15 | length 933.2
  Top w7.87: H2.3@246.85,303.54 327.17,303.54 327.36,303.74 385.83,245.28 599.21,245.28 609.06,235.43 1063.78,235.43 v1(1096.46,202.76)
  Bottom w7.87: v1(1096.46,202.76) 1097.24,201.97 U1.15@1097.24,161.42
P2.4: H2.4 U1.14 | length 1105.2
  Top w7.87: H2.4@146.85,303.54 146.85,304.72 192.52,350.39 322.34,350.39 409.45,263.29 605.02,263.29 617.32,250.98 1081.69,250.98 v1(1127.95,204.72)
  Bottom w7.87: v1(1127.95,204.72) 1128.74,203.94 U1.14@1128.74,161.42
SW_CS: H2.10 U1.11 | length 1323.6
  Top w7.87: H2.10@146.85,603.54 149.2,603.54 203.54,549.2 203.54,547.24 292.52,547.24 314.57,525.2 314.57,454.33 425.59,343.31 597.05,343.31 674.8,265.55 1155.71,265.55 v1(1222.44,198.82)
  Bottom w7.87: v1(1222.44,198.82) 1223.23,198.03 U1.11@1223.23,161.42
SW_MISO: H2.1 U1.13 | length 1031
  Top w7.87: H2.1@246.85,203.54 251.68,203.54 255.02,200.2 257.58,200.2 314.17,143.6 600.39,143.6 663.78,206.99 1025.89,206.99 1059.65,173.23 1135.33,173.23 1156.59,194.49 1156.99,194.49 1156.99,198.33 v1(1159.45,200.79)
  Bottom w7.87: v1(1159.45,200.79) 1160.24,200 U1.13@1160.24,161.42
SW_MOSI: H2.2 U1.16 | length 1059
  Top w7.87: H2.2@146.85,203.54 194.88,251.57 329.92,251.57 422.44,159.06 594.49,159.06 656.3,220.87 1048.03,220.87 v1(1074.41,194.49)
  Bottom w7.87: U1.16@1065.75,161.42 1065.75,185.83 v1(1074.41,194.49)
VCC: C4.1 H2.7 H4.7 JP1.1 R3.2 R4.2 R14.1 U2.5 U3.8 U4.8 | length 3963.7
  Top w7.87: 67.32,695.28 69.69,695.28
  Top w11.81: 69.69,695.28 R3.2@227.95,695.28
  Top w23.62: H2.7@246.85,503.54 246,502.69 246,496.61 205.51,456.12 205.51,454.72 67.32,454.72 ; JP1.1@468.11,732.28 468.11,733.46 436.61,764.96 125.2,764.96 67.32,707.09 67.32,695.28 67.32,454.72 ; C4.1@1083.07,105.59 1074.49,114.17 662.2,114.17 639.37,91.34 125.2,91.34 67.32,149.21 67.32,454.72
  Top w31.5: C4.1@1083.07,105.59 1095.2,117.72 1283.86,117.72 1333.46,166.54 v2(1348.03,166.54)
  Bottom w7.87: 852.76,524.41 853.94,525.59
  Bottom w11.81: H4.7@561.81,503.54 575.72,503.54 620.08,547.9 620.08,595.28 644.88,620.08 798.43,620.08 832.48,586.02 U3.8@832.48,524.41 ; U4.8@805.51,409.45 805.51,455.91 832.68,483.07 832.68,524.21 U3.8@832.48,524.41 ; 852.76,524.41 U3.8@832.48,524.41 ; 853.94,525.59 872.44,544.09 R4.2@930.71,544.09
  Bottom w23.62: H2.7@246.85,503.54 277.95,472.44 279.92,472.44 298.82,453.54 511.81,453.54 H4.7@561.81,503.54
  Bottom w31.5: v2(1348.03,166.54) 1400.29,165.86 1455.51,221.08 R14.1@1516.93,221.08 1565.57,221.08 U2.5@1570.87,226.38
VDD: C1.2 D2.2 H3.1 JP1.2 R1.2 U1.6 | length 2111.5
  Top w23.62: JP1.2@568.11,732.28 589.17,711.22 589.57,711.22 605.12,695.67 1066.54,695.67 1231.1,531.1 1231.1,494.88 ; D2.2@1209.16,370.87 1231.1,392.81 1231.1,494.88 ; v1(1397.64,295.28) 1490.94,388.58 v1@1518.9,388.58 ; v1(1519.69,387.8) v1@1518.9,388.58 ; 1231.1,494.88 1412.6,494.88 v1@1518.9,388.58
  Bottom w11.81: H3.1@1192.91,59.06 1190.76,59.27 1190.63,59.27 1161.32,88.58 1087.4,88.58 1045.28,130.71 1044.88,130.71 1044.88,195.28 1144.09,294.49 1151.97,294.49 1152.76,295.28 U1.6@1357.09,295.28
  Bottom w13.78: v1(1397.64,295.28) 1424.02,295.28 C1.2@1430.32,301.57
  Bottom w23.62: U1.6@1357.09,295.28 v1(1397.64,295.28) ; R1.2@1489.76,391.34 1516.14,391.34 v1(1519.69,387.8)
VPP: C2.2 H2.8 H4.8 R4.1 R6.2 | length 1095.5
  Bottom w7.87: H2.8@146.85,503.54 194.88,551.57 413.78,551.57 H4.8@461.81,503.54 508.27,550 509.06,550 509.84,550.79 582.68,550.79 601.57,569.69 601.57,607.09 637.4,642.91 878.74,642.91 966.14,555.51 966.14,544.09 966.14,542.91 968.9,542.91 R4.1@970.08,544.09 C2.2@970.08,501.58 970.08,499.61 R6.2@928.35,457.87
pads on no net: C1_1.1 C1_1.2 C1_1_1.1 C1_1_1.2 C1_2.1 C1_2.2 C1_2_1.1 C1_2_1.2 C1_3.1 C1_3.2 C1_3_1.1 C1_3_1.2 C1_4.1 C1_4.2 C2_1.1 C2_1.2 C2_1_1.1 C2_1_1.2 C2_2.1 C2_2.2 C2_2_1.1 C2_2_1.2 C2_3.1 C2_3.2 C2_3_1.1 C2_3_1.2 C2_4.1 C2_4.2 C3_1.1 C3_1.2 C3_1_1.1 C3_1_1.2 C3_2.1 C3_2.2 C3_2_1.1 C3_2_1.2 C3_3.1 C3_3.2 C3_3_1.1 C3_3_1.2 C3_4.1 C3_4.2 C4_1.1 C4_1.2 C4_1_1.1 C4_1_1.2 C4_2.1 C4_2.2 C4_2_1.1 C4_2_1.2 C4_3.1 C4_3.2 C4_3_1.1 C4_3_1.2 C4_4.1 C4_4.2 C5_1.1 C5_1.2 C5_1_1.1 C5_1_1.2 C5_2.1 C5_2.2 C5_2_1.1 C5_2_1.2 C5_3.1 C5_3.2 C5_3_1.1 C5_3_1.2 C5_4.1 C5_4.2 C6_1.1 C6_1.2 C6_1_1.1 C6_1_1.2 C6_2.1 C6_2.2 C6_2_1.1 C6_2_1.2 C6_3.1 C6_3.2 C6_3_1.1 C6_3_1.2 C6_4.1 C6_4.2 C7_1.1 C7_1.2 C7_1_1.1 C7_1_1.2 C7_2.1 C7_2.2 C7_2_1.1 C7_2_1.2 C7_3.1 C7_3.2 C7_3_1.1 C7_3_1.2 C7_4.1 C7_4.2 D1_1.1 D1_1.2 D1_1_1.1 D1_1_1.2 D1_2.1 D1_2.2 D1_2_1.1 D1_2_1.2 D1_3.1 D1_3.2 D1_3_1.1 D1_3_1.2 D1_4.1 D1_4.2 D2_1.1 D2_1.2 D2_1_1.1 D2_1_1.2 D2_2.1 D2_2.2 D2_2_1.1 D2_2_1.2 D2_3.1 D2_3.2 D2_3_1.1 D2_3_1.2 D2_4.1 D2_4.2 H1_1.1 H1_1.2 H1_1.3 H1_1.4 H1_1_1.1 H1_1_1.2 H1_1_1.3 H1_1_1.4 H1_2.1 H1_2.2 H1_2.3 H1_2.4 H1_2_1.1 H1_2_1.2 H1_2_1.3 H1_2_1.4 H1_3.1 H1_3.2 H1_3.3 H1_3.4 H1_3_1.1 H1_3_1.2 H1_3_1.3 H1_3_1.4 H1_4.1 H1_4.2 H1_4.3 H1_4.4 H2_1.1 H2_1.2 H2_1.3 H2_1.4 H2_1.5 H2_1.6 H2_1.7 H2_1.8 H2_1.9 H2_1.10 H2_1_1.1 H2_1_1.2 H2_1_1.3 H2_1_1.4 H2_1_1.5 H2_1_1.6 H2_1_1.7 H2_1_1.8 H2_1_1.9 H2_1_1.10 H2_2.1 H2_2.2 H2_2.3 H2_2.4 H2_2.5 H2_2.6 H2_2.7 H2_2.8 H2_2.9 H2_2.10 H2_2_1.1 H2_2_1.2 H2_2_1.3 H2_2_1.4 H2_2_1.5 H2_2_1.6 H2_2_1.7 H2_2_1.8 H2_2_1.9 H2_2_1.10 H2_3.1 H2_3.2 H2_3.3 H2_3.4 H2_3.5 H2_3.6 H2_3.7 H2_3.8 H2_3.9 H2_3.10 H2_3_1.1 H2_3_1.2 H2_3_1.3 H2_3_1.4 H2_3_1.5 H2_3_1.6 H2_3_1.7 H2_3_1.8 H2_3_1.9 H2_3_1.10 H2_4.1 H2_4.2 H2_4.3 H2_4.4 H2_4.5 H2_4.6 H2_4.7 H2_4.8 H2_4.9 H2_4.10 H3_1.1 H3_1.2 H3_1.3 H3_1.4 H3_1_1.1 H3_1_1.2 H3_1_1.3 H3_1_1.4 H3_2.1 H3_2.2 H3_2.3 H3_2.4 H3_2_1.1 H3_2_1.2 H3_2_1.3 H3_2_1.4 H3_3.1 H3_3.2 H3_3.3 H3_3.4 H3_3_1.1 H3_3_1.2 H3_3_1.3 H3_3_1.4 H3_4.1 H3_4.2 H3_4.3 H3_4.4 H4_1.1 H4_1.2 H4_1.3 H4_1.4 H4_1.5 H4_1.6 H4_1.7 H4_1.8 H4_1.9 H4_1.10 H4_1_1.1 H4_1_1.2 H4_1_1.3 H4_1_1.4 H4_1_1.5 H4_1_1.6 H4_1_1.7 H4_1_1.8 H4_1_1.9 H4_1_1.10 H4_2.1 H4_2.2 H4_2.3 H4_2.4 H4_2.5 H4_2.6 H4_2.7 H4_2.8 H4_2.9 H4_2.10 H4_2_1.1 H4_2_1.2 H4_2_1.3 H4_2_1.4 H4_2_1.5 H4_2_1.6 H4_2_1.7 H4_2_1.8 H4_2_1.9 H4_2_1.10 H4_3.1 H4_3.2 H4_3.3 H4_3.4 H4_3.5 H4_3.6 H4_3.7 H4_3.8 H4_3.9 H4_3.10 H4_3_1.1 H4_3_1.2 H4_3_1.3 H4_3_1.4 H4_3_1.5 H4_3_1.6 H4_3_1.7 H4_3_1.8 H4_3_1.9 H4_3_1.10 H4_4.1 H4_4.2 H4_4.3 H4_4.4 H4_4.5 H4_4.6 H4_4.7 H4_4.8 H4_4.9 H4_4.10 J1_1.1 J1_1.2 J1_1.3 J1_1.4 J1_1.5 J1_1.6 J1_1_1.1 J1_1_1.2 J1_1_1.3 J1_1_1.4 J1_1_1.5 J1_1_1.6 J1_2.1 J1_2.2 J1_2.3 J1_2.4 J1_2.5 J1_2.6 J1_2_1.1 J1_2_1.2 J1_2_1.3 J1_2_1.4 J1_2_1.5 J1_2_1.6 J1_3.1 J1_3.2 J1_3.3 J1_3.4 J1_3.5 J1_3.6 J1_3_1.1 J1_3_1.2 J1_3_1.3 J1_3_1.4 J1_3_1.5 J1_3_1.6 J1_4.1 J1_4.2 J1_4.3 J1_4.4 J1_4.5 J1_4.6 JP1_1.1 JP1_1.2 JP1_1_1.1 JP1_1_1.2 JP1_2.1 JP1_2.2 JP1_2_1.1 JP1_2_1.2 JP1_3.1 JP1_3.2 JP1_3_1.1 JP1_3_1.2 JP1_4.1 JP1_4.2 R1_1.1 R1_1.2 R1_1_1.1 R1_1_1.2 R1_2.1 R1_2.2 R1_2_1.1 R1_2_1.2 R1_3.1 R1_3.2 R1_3_1.1 R1_3_1.2 R1_4.1 R1_4.2 R2_1.1 R2_1.2 R2_1_1.1 R2_1_1.2 R2_2.1 R2_2.2 R2_2_1.1 R2_2_1.2 R2_3.1 R2_3.2 R2_3_1.1 R2_3_1.2 R2_4.1 R2_4.2 R3_1.1 R3_1.2 R3_1_1.1 R3_1_1.2 R3_2.1 R3_2.2 R3_2_1.1 R3_2_1.2 R3_3.1 R3_3.2 R3_3_1.1 R3_3_1.2 R3_4.1 R3_4.2 R4_1.1 R4_1.2 R4_1_1.1 R4_1_1.2 R4_2.1 R4_2.2 R4_2_1.1 R4_2_1.2 R4_3.1 R4_3.2 R4_3_1.1 R4_3_1.2 R4_4.1 R4_4.2 R5_1.1 R5_1.2 R5_1_1.1 R5_1_1.2 R5_2.1 R5_2.2 R5_2_1.1 R5_2_1.2 R5_3.1 R5_3.2 R5_3_1.1 R5_3_1.2 R5_4.1 R5_4.2 R6_1.1 R6_1.2 R6_1_1.1 R6_1_1.2 R6_2.1 R6_2.2 R6_2_1.1 R6_2_1.2 R6_3.1 R6_3.2 R6_3_1.1 R6_3_1.2 R6_4.1 R6_4.2 R7_1.1 R7_1.2 R7_1_1.1 R7_1_1.2 R7_2.1 R7_2.2 R7_2_1.1 R7_2_1.2 R7_3.1 R7_3.2 R7_3_1.1 R7_3_1.2 R7_4.1 R7_4.2 R8_1.1 R8_1.2 R8_1_1.1 R8_1_1.2 R8_2.1 R8_2.2 R8_2_1.1 R8_2_1.2 R8_3.1 R8_3.2 R8_3_1.1 R8_3_1.2 R8_4.1 R8_4.2 R9_1.1 R9_1.2 R9_1_1.1 R9_1_1.2 R9_2.1 R9_2.2 R9_2_1.1 R9_2_1.2 R9_3.1 R9_3.2 R9_3_1.1 R9_3_1.2 R9_4.1 R9_4.2 R10_1.1 R10_1.2 R10_1_1.1 R10_1_1.2 R10_2.1 R10_2.2 R10_2_1.1 R10_2_1.2 R10_3.1 R10_3.2 R10_3_1.1 R10_3_1.2 R10_4.1 R10_4.2 R11_1.1 R11_1.2 R11_1_1.1 R11_1_1.2 R11_2.1 R11_2.2 R11_2_1.1 R11_2_1.2 R11_3.1 R11_3.2 R11_3_1.1 R11_3_1.2 R11_4.1 R11_4.2 R13_1.1 R13_1.2 R13_1_1.1 R13_1_1.2 R13_2.1 R13_2.2 R13_2_1.1 R13_2_1.2 R13_3.1 R13_3.2 R13_3_1.1 R13_3_1.2 R13_4.1 R13_4.2 R14_1.1 R14_1.2 R14_1_1.1 R14_1_1.2 R14_2.1 R14_2.2 R14_2_1.1 R14_2_1.2 R14_3.1 R14_3.2 R14_3_1.1 R14_3_1.2 R14_4.1 R14_4.2 S1_1.1 S1_1.2 S1_1.3 S1_1.4 S1_1_1.1 S1_1_1.2 S1_1_1.3 S1_1_1.4 S1_2.1 S1_2.2 S1_2.3 S1_2.4 S1_2_1.1 S1_2_1.2 S1_2_1.3 S1_2_1.4 S1_3.1 S1_3.2 S1_3.3 S1_3.4 S1_3_1.1 S1_3_1.2 S1_3_1.3 S1_3_1.4 S1_4.1 S1_4.2 S1_4.3 S1_4.4 U1.20 U1.22 U1.23 U1_1.1 U1_1.2 U1_1.3 U1_1.4 U1_1.5 U1_1.6 U1_1.7 U1_1.8 U1_1.9 U1_1.10 U1_1.11 U1_1.12 U1_1.13 U1_1.14 U1_1.15 U1_1.16 U1_1.17 U1_1.18 U1_1.19 U1_1.20 U1_1.21 U1_1.22 U1_1.23 U1_1.24 U1_1.25 U1_1.26 U1_1.27 U1_1.28 U1_1.29 U1_1.30 U1_1.31 U1_1.32 U1_1_1.1 U1_1_1.2 U1_1_1.3 U1_1_1.4 U1_1_1.5 U1_1_1.6 U1_1_1.7 U1_1_1.8 U1_1_1.9 U1_1_1.10 U1_1_1.11 U1_1_1.12 U1_1_1.13 U1_1_1.14 U1_1_1.15 U1_1_1.16 U1_1_1.17 U1_1_1.18 U1_1_1.19 U1_1_1.20 U1_1_1.21 U1_1_1.22 U1_1_1.23 U1_1_1.24 U1_1_1.25 U1_1_1.26 U1_1_1.27 U1_1_1.28 U1_1_1.29 U1_1_1.30 U1_1_1.31 U1_1_1.32 U1_2.1 U1_2.2 U1_2.3 U1_2.4 U1_2.5 U1_2.6 U1_2.7 U1_2.8 U1_2.9 U1_2.10 U1_2.11 U1_2.12 U1_2.13 U1_2.14 U1_2.15 U1_2.16 U1_2.17 U1_2.18 U1_2.19 U1_2.20 U1_2.21 U1_2.22 U1_2.23 U1_2.24 U1_2.25 U1_2.26 U1_2.27 U1_2.28 U1_2.29 U1_2.30 U1_2.31 U1_2.32 U1_2_1.1 U1_2_1.2 U1_2_1.3 U1_2_1.4 U1_2_1.5 U1_2_1.6 U1_2_1.7 U1_2_1.8 U1_2_1.9 U1_2_1.10 U1_2_1.11 U1_2_1.12 U1_2_1.13 U1_2_1.14 U1_2_1.15 U1_2_1.16 U1_2_1.17 U1_2_1.18 U1_2_1.19 U1_2_1.20 U1_2_1.21 U1_2_1.22 U1_2_1.23 U1_2_1.24 U1_2_1.25 U1_2_1.26 U1_2_1.27 U1_2_1.28 U1_2_1.29 U1_2_1.30 U1_2_1.31 U1_2_1.32 U1_3.1 U1_3.2 U1_3.3 U1_3.4 U1_3.5 U1_3.6 U1_3.7 U1_3.8 U1_3.9 U1_3.10 U1_3.11 U1_3.12 U1_3.13 U1_3.14 U1_3.15 U1_3.16 U1_3.17 U1_3.18 U1_3.19 U1_3.20 U1_3.21 U1_3.22 U1_3.23 U1_3.24 U1_3.25 U1_3.26 U1_3.27 U1_3.28 U1_3.29 U1_3.30 U1_3.31 U1_3.32 U1_3_1.1 U1_3_1.2 U1_3_1.3 U1_3_1.4 U1_3_1.5 U1_3_1.6 U1_3_1.7 U1_3_1.8 U1_3_1.9 U1_3_1.10 U1_3_1.11 U1_3_1.12 U1_3_1.13 U1_3_1.14 U1_3_1.15 U1_3_1.16 U1_3_1.17 U1_3_1.18 U1_3_1.19 U1_3_1.20 U1_3_1.21 U1_3_1.22 U1_3_1.23 U1_3_1.24 U1_3_1.25 U1_3_1.26 U1_3_1.27 U1_3_1.28 U1_3_1.29 U1_3_1.30 U1_3_1.31 U1_3_1.32 U1_4.1 U1_4.2 U1_4.3 U1_4.4 U1_4.5 U1_4.6 U1_4.7 U1_4.8 U1_4.9 U1_4.10 U1_4.11 U1_4.12 U1_4.13 U1_4.14 U1_4.15 U1_4.16 U1_4.17 U1_4.18 U1_4.19 U1_4.20 U1_4.21 U1_4.22 U1_4.23 U1_4.24 U1_4.25 U1_4.26 U1_4.27 U1_4.28 U1_4.29 U1_4.30 U1_4.31 U1_4.32 U2_1.1 U2_1.2 U2_1.3 U2_1.4 U2_1.5 U2_1_1.1 U2_1_1.2 U2_1_1.3 U2_1_1.4 U2_1_1.5 U2_2.1 U2_2.2 U2_2.3 U2_2.4 U2_2.5 U2_2_1.1 U2_2_1.2 U2_2_1.3 U2_2_1.4 U2_2_1.5 U2_3.1 U2_3.2 U2_3.3 U2_3.4 U2_3.5 U2_3_1.1 U2_3_1.2 U2_3_1.3 U2_3_1.4 U2_3_1.5 U2_4.1 U2_4.2 U2_4.3 U2_4.4 U2_4.5 U3_1.1 U3_1.2 U3_1.3 U3_1.4 U3_1.5 U3_1.6 U3_1.7 U3_1.8 U3_1_1.1 U3_1_1.2 U3_1_1.3 U3_1_1.4 U3_1_1.5 U3_1_1.6 U3_1_1.7 U3_1_1.8 U3_2.1 U3_2.2 U3_2.3 U3_2.4 U3_2.5 U3_2.6 U3_2.7 U3_2.8 U3_2_1.1 U3_2_1.2 U3_2_1.3 U3_2_1.4 U3_2_1.5 U3_2_1.6 U3_2_1.7 U3_2_1.8 U3_3.1 U3_3.2 U3_3.3 U3_3.4 U3_3.5 U3_3.6 U3_3.7 U3_3.8 U3_3_1.1 U3_3_1.2 U3_3_1.3 U3_3_1.4 U3_3_1.5 U3_3_1.6 U3_3_1.7 U3_3_1.8 U3_4.1 U3_4.2 U3_4.3 U3_4.4 U3_4.5 U3_4.6 U3_4.7 U3_4.8 U4_1.1 U4_1.2 U4_1.3 U4_1.4 U4_1.5 U4_1.6 U4_1.7 U4_1.8 U4_1_1.1 U4_1_1.2 U4_1_1.3 U4_1_1.4 U4_1_1.5 U4_1_1.6 U4_1_1.7 U4_1_1.8 U4_2.1 U4_2.2 U4_2.3 U4_2.4 U4_2.5 U4_2.6 U4_2.7 U4_2.8 U4_2_1.1 U4_2_1.2 U4_2_1.3 U4_2_1.4 U4_2_1.5 U4_2_1.6 U4_2_1.7 U4_2_1.8 U4_3.1 U4_3.2 U4_3.3 U4_3.4 U4_3.5 U4_3.6 U4_3.7 U4_3.8 U4_3_1.1 U4_3_1.2 U4_3_1.3 U4_3_1.4 U4_3_1.5 U4_3_1.6 U4_3_1.7 U4_3_1.8 U4_4.1 U4_4.2 U4_4.3 U4_4.4 U4_4.5 U4_4.6 U4_4.7 U4_4.8 W1_1.1 W1_1.2 W1_1_1.1 W1_1_1.2 W1_2.1 W1_2.2 W1_2_1.1 W1_2_1.2 W1_3.1 W1_3.2 W1_3_1.1 W1_3_1.2 W1_4.1 W1_4.2 X1_1.1 X1_1.2 X1_1.3 X1_1.4 X1_1_1.1 X1_1_1.2 X1_1_1.3 X1_1_1.4 X1_2.1 X1_2.2 X1_2.3 X1_2.4 X1_2_1.1 X1_2_1.2 X1_2_1.3 X1_2_1.4 X1_3.1 X1_3.2 X1_3.3 X1_3.4 X1_3_1.1 X1_3_1.2 X1_3_1.3 X1_3_1.4 X1_4.1 X1_4.2 X1_4.3 X1_4.4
